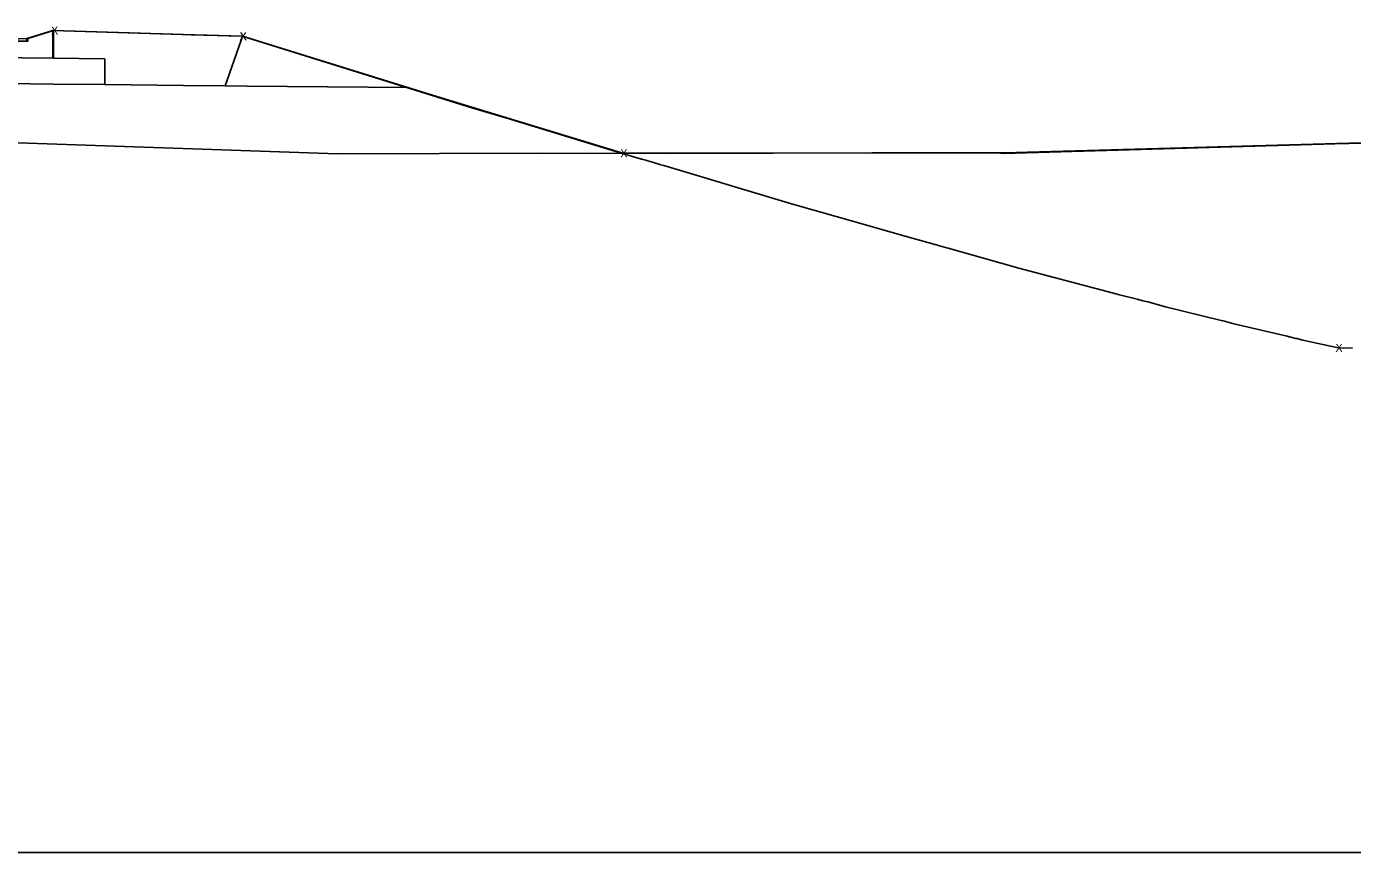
# Model space of a CAD drawing. Extents: x -26 to 303, y -16 to 6048.
# Drawn here: x 173.38 to 213.16, y 5000 to 5024.76 of the extents above; entities that cross this region are included whole.
import ezdxf

# ---------------------------------------------------------------- set-up
doc = ezdxf.new("R2010")
doc.units = 0
for name, color, linetype in [('CONST_DCH', 7, 'Continuous'), ('CONST_LV3', 7, 'Continuous'), ('DTM_P_FINISHED_GRADE2', 7, 'Continuous'), ('DTM_TEMP_DROP', 7, 'Continuous'), ('DTM_X_GROUND', 7, 'Continuous'), ('X_PROFILES_1', 7, 'Continuous'), ('XS_CELL', 7, 'Continuous'), ('XS_M_SHAPES_EARTHWORK', 7, 'Continuous'), ('XS_P_CONCRETE', 7, 'Continuous'), ('XS_P_GROUND', 7, 'Continuous'), ('XS_P_SHOULDER', 7, 'Continuous'), ('XS_P_SUBGRADE_GRANULAR', 7, 'Continuous'), ('XS_P_SUBGRADE_GRANULAR_B', 7, 'Continuous')]:
    doc.layers.add(name, color=color, linetype=linetype)

msp = doc.modelspace()

# ---------------------------------------------------------------- linework, layer by layer
at = {"layer": 'CONST_LV3'}
for points in [[(171.334, 5024.346), (171.334, 5023.846), (174.172, 5023.811), (174.172, 5024.644), (173.395, 5024.404), (173.394, 5024.32), (171.334, 5024.346)], [(174.172, 5024.644), (178.038, 5024.525), (178.076, 5024.524), (178.094, 5024.523), (178.318, 5024.516), (178.408, 5024.514), (178.707, 5024.505), (178.788, 5024.503), (179.112, 5024.493), (179.164, 5024.492), (179.848, 5024.472)], [(174.172, 5024.644), (178.038, 5024.525), (178.076, 5024.524), (178.094, 5024.523), (178.318, 5024.516), (178.408, 5024.514), (178.707, 5024.505), (178.788, 5024.503), (179.112, 5024.493), (179.164, 5024.492), (179.848, 5024.472), (186.776, 5022.319), (187.787, 5022.018), (190.963, 5021.048), (191.835, 5020.792), (191.853, 5020.787), (191.859, 5020.785), (191.874, 5020.781), (191.879, 5020.779), (191.962, 5020.754), (191.991, 5020.746), (192.118, 5020.707), (192.162, 5020.695), (192.413, 5020.619), (192.503, 5020.593), (196.326, 5019.45), (198.34, 5018.882), (199.561, 5018.525), (200.598, 5018.24), (200.623, 5018.232), (200.648, 5018.225), (200.686, 5018.215), (200.724, 5018.204), (200.874, 5018.161), (201.032, 5018.118), (203.151, 5017.516), (205.951, 5016.783), (206.17, 5016.722), (206.698, 5016.588), (206.701, 5016.587), (206.711, 5016.584), (206.718, 5016.582), (206.735, 5016.578), (206.754, 5016.573), (206.809, 5016.559), (206.863, 5016.544), (207.015, 5016.506), (207.546, 5016.362), (209.217, 5015.953), (209.225, 5015.951), (209.269, 5015.94), (209.276, 5015.938), (209.315, 5015.929), (209.596, 5015.855), (211.194, 5015.477), (211.197, 5015.476), (211.232, 5015.468), (211.232, 5015.468), (211.245, 5015.465), (211.245, 5015.465), (211.248, 5015.465), (211.263, 5015.461), (211.462, 5015.414), (211.463, 5015.414), (211.49, 5015.408), (211.663, 5015.364), (212.725, 5015.129)], [(174.198, 5024.644), (178.095, 5024.523), (179.861, 5024.472), (185.687, 5022.666), (191.273, 5020.964)], [(175.731, 5023.022), (175.732, 5023.793), (174.198, 5023.811)]]:
    msp.add_lwpolyline(points, dxfattribs=at)
at = {"layer": 'DTM_P_FINISHED_GRADE2'}
msp.add_lwpolyline([(133.416, 5024.418), (150, 5024.744), (157.477, 5024.598), (171.377, 5024.346), (172.884, 5024.328), (173.423, 5024.321), (173.424, 5024.341), (173.425, 5024.404), (174.034, 5024.594), (174.198, 5024.644), (178.095, 5024.523), (179.45, 5024.483), (179.861, 5024.472), (185.687, 5022.666), (191.273, 5020.964)], dxfattribs=at)
at = {"layer": 'DTM_X_GROUND'}
for points in [[(133.416, 5024.418), (150, 5024.744), (157.477, 5024.598), (171.377, 5024.346), (172.886, 5024.389), (173.425, 5024.404), (174.034, 5024.594), (174.198, 5024.644), (178.095, 5024.523), (179.45, 5024.483), (179.861, 5024.472), (185.687, 5022.666), (191.273, 5020.964), (191.415, 5020.964), (192.704, 5020.965), (193.791, 5020.965), (198.744, 5020.982), (198.836, 5020.973), (202.602, 5020.968), (202.694, 5020.961), (212.964, 5021.26), (213.045, 5021.256), (215.433, 5021.276)], [(138.671, 5021.203), (142.371, 5021.197), (148.68, 5021.201), (157.475, 5021.251), (160.23, 5021.247), (166.193, 5021.433), (168.121, 5021.386), (170.323, 5021.316), (171.962, 5021.321), (182.715, 5020.947), (188.823, 5020.967), (192.704, 5020.962), (198.836, 5020.982), (202.694, 5020.977), (213.045, 5021.268), (215.433, 5021.276)]]:
    msp.add_lwpolyline(points, dxfattribs=at)
at = {"layer": 'XS_CELL'}
msp.add_line((150, 5000), (300, 5000), dxfattribs=at)
at = {"layer": 'XS_M_SHAPES_EARTHWORK'}
msp.add_lwpolyline([(171.334, 5022.472), (171.377, 5022.471), (171.377, 5022.742), (171.377, 5022.95), (171.377, 5023.075), (174.198, 5023.04), (175.731, 5023.022), (178.095, 5022.995), (179.338, 5022.983), (180.001, 5022.978), (184.821, 5022.934), (179.861, 5024.472), (179.45, 5024.483), (178.095, 5024.523), (174.198, 5024.644), (174.034, 5024.594), (173.425, 5024.404), (172.886, 5024.389), (171.377, 5024.346), (167.686, 5024.413), (170.108, 5024.368), (171.334, 5024.346)], close=True, dxfattribs=at)
at = {"layer": 'XS_P_CONCRETE'}
msp.add_lwpolyline([(171.377, 5024.346), (171.377, 5023.846), (174.198, 5023.811), (174.198, 5024.644), (173.425, 5024.404), (173.423, 5024.321), (171.377, 5024.346)], dxfattribs=at)
at = {"layer": 'XS_P_GROUND'}
for points in [[(212.725, 5015.129), (211.663, 5015.364), (211.49, 5015.408), (211.463, 5015.414), (211.462, 5015.414), (211.263, 5015.461), (211.248, 5015.465), (211.245, 5015.465), (211.245, 5015.465), (211.232, 5015.468), (211.232, 5015.468), (211.197, 5015.476), (211.194, 5015.477), (209.596, 5015.855), (209.315, 5015.929), (209.276, 5015.938), (209.269, 5015.94), (209.225, 5015.951), (209.217, 5015.953), (207.546, 5016.362), (207.015, 5016.506), (206.863, 5016.544), (206.809, 5016.559), (206.754, 5016.573), (206.735, 5016.578), (206.718, 5016.582), (206.711, 5016.584), (206.701, 5016.587), (206.698, 5016.588), (206.17, 5016.722), (205.951, 5016.783), (203.151, 5017.516), (201.032, 5018.118), (200.874, 5018.161), (200.724, 5018.204), (200.686, 5018.215), (200.648, 5018.225), (200.623, 5018.232), (200.598, 5018.24), (199.561, 5018.525), (198.34, 5018.882), (196.326, 5019.45), (192.503, 5020.593), (192.413, 5020.619), (192.162, 5020.695), (192.118, 5020.707), (191.991, 5020.746), (191.962, 5020.754), (191.879, 5020.779), (191.874, 5020.781), (191.859, 5020.785), (191.853, 5020.787), (191.835, 5020.792), (190.963, 5021.048), (187.787, 5022.018), (186.776, 5022.319), (179.848, 5024.472)], [(191.273, 5020.964), (185.687, 5022.666), (179.861, 5024.472)], [(213.156, 5015.122), (213.149, 5015.123), (212.725, 5015.129)]]:
    msp.add_lwpolyline(points, dxfattribs=at)
at = {"layer": 'XS_P_SHOULDER'}
msp.add_lwpolyline([(174.198, 5024.644), (178.095, 5024.523), (179.861, 5024.472)], dxfattribs=at)
at = {"layer": 'XS_P_SUBGRADE_GRANULAR'}
for points in [[(174.198, 5023.04), (171.377, 5023.075)], [(175.731, 5023.022), (174.198, 5023.04)]]:
    msp.add_lwpolyline(points, dxfattribs=at)
at = {"layer": 'XS_P_SUBGRADE_GRANULAR_B'}
for points in [[(179.861, 5024.472), (179.809, 5024.325), (179.338, 5022.983)], [(175.731, 5023.022), (178.095, 5022.995), (179.338, 5022.983)], [(184.84, 5022.934), (180.001, 5022.978), (179.338, 5022.983)]]:
    msp.add_lwpolyline(points, dxfattribs=at)

# ---------------------------------------------------------------- texts
at = {"layer": 'CONST_DCH'}
msp.add_text('X', height=0.24, dxfattribs=at).set_placement((212.647, 5015.009))
at = {"layer": 'DTM_TEMP_DROP'}
for p in [(191.195, 5020.844), (212.647, 5015.009)]:
    msp.add_text('X', height=0.24, dxfattribs=at).set_placement(p)
at = {"layer": 'X_PROFILES_1'}
msp.add_text('X', height=0.24, dxfattribs=at).set_placement((179.769, 5024.352))
at = {"layer": 'XS_P_GROUND'}
for p in [(174.119, 5024.524), (179.782, 5024.352)]:
    msp.add_text('X', height=0.24, dxfattribs=at).set_placement(p)
at = {"layer": 'XS_P_SUBGRADE_GRANULAR'}
msp.add_text('X', height=0.24, dxfattribs=at).set_placement((191.195, 5020.844))

doc.saveas('drawing.dxf')
